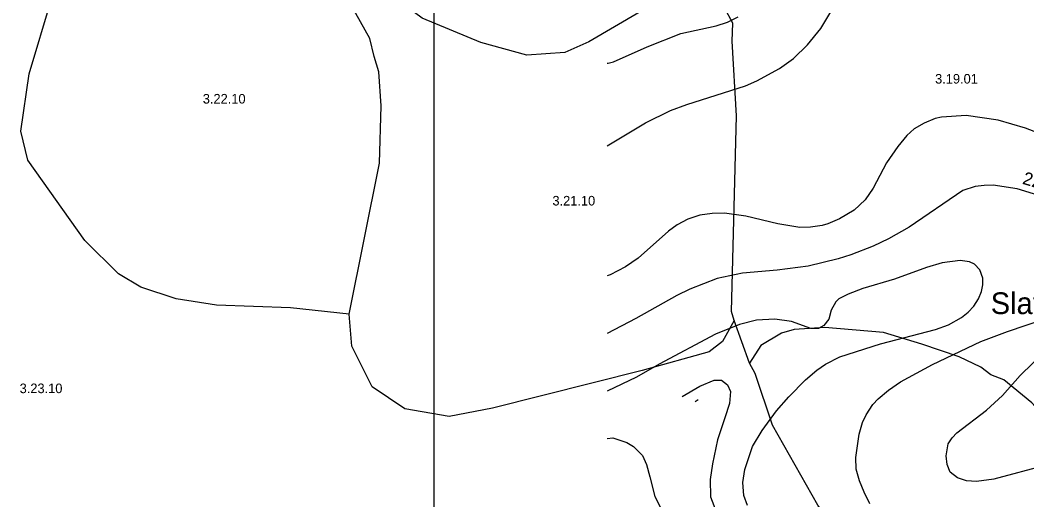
# Model space of a CAD drawing. Extents: x -662500 to -655523, y -1056000 to -1049993.
# Drawn here: x -662052 to -661264, y -1052458 to -1052083 of the extents above; entities that cross this region are included whole.
import ezdxf

# ---------------------------------------------------------------- set-up
doc = ezdxf.new("R2010")
doc.units = 0
for name, color, linetype in [('58', 7, 'Continuous'), ('Vrstva 24', 7, 'Continuous'), ('Vrstva 7', 7, 'Continuous'), ('Vrstva 9', 7, 'Continuous')]:
    doc.layers.add(name, color=color, linetype=linetype)

msp = doc.modelspace()

# ---------------------------------------------------------------- linework, layer by layer
at = {"layer": 'Vrstva 24'}
for points in [[(-661794, -1052312.5), (-661840, -1052307.5), (-661898, -1052305.5), (-661929.5, -1052300.5), (-661957, -1052291.5), (-661974.5, -1052281), (-662001, -1052255), (-662045.5, -1052192), (-662051, -1052169.5), (-662044.5, -1052124.5), (-662027, -1052066), (-662005.5, -1052025.5), (-661977.17, -1052000), (-661965.5, -1051989.5), (-661936, -1051957)], [(-661794, -1052312.5), (-661770.5, -1052194.5), (-661769, -1052149.5), (-661771, -1052123), (-661774.5, -1052111), (-661778, -1052097), (-661789, -1052077.5), (-661800, -1052057), (-661815.5, -1052036)], [(-661493, -1052317.5), (-661495, -1052310.5), (-661491, -1052157.5), (-661494.5, -1052099), (-661494, -1052085), (-661500.5, -1052073), (-661505, -1052066), (-661512.5, -1052062), (-661538.5, -1052064.5), (-661566.5, -1052076), (-661606.5, -1052099.5), (-661625.5, -1052108), (-661655, -1052110), (-661691, -1052100), (-661737, -1052081), (-661750, -1052071.5)], [(-661493, -1052317.5), (-661502, -1052334), (-661512.5, -1052342), (-661565, -1052356.5), (-661682, -1052386), (-661716, -1052392.5), (-661750.5, -1052386.5), (-661776, -1052369.5), (-661792, -1052337.5), (-661794, -1052312.5)], [(-661481, -1052351), (-661493, -1052317.5)], [(-661227, -1052423), (-661235.5, -1052409), (-661260, -1052382), (-661282, -1052364), (-661292, -1052360), (-661300, -1052354), (-661317, -1052346), (-661346, -1052336), (-661376, -1052327), (-661422, -1052323), (-661446, -1052324.5), (-661456, -1052327.5), (-661472, -1052337), (-661481, -1052351)], [(-661304, -1052572.5), (-661358, -1052540), (-661388.5, -1052512), (-661390.5, -1052507), (-661393, -1052508.5), (-661427.5, -1052462), (-661463, -1052399.5), (-661476.5, -1052359), (-661481, -1052351)]]:
    msp.add_lwpolyline(points, dxfattribs=at)
at = {"layer": 'Vrstva 7'}
for p, q in [((-661425.05, -1052089.09), (-661409.74, -1052063.58)), ((-661534.59, -1052093.06), (-661507.1, -1052087.11)), ((-661507.1, -1052087.11), (-661498.03, -1052084.13)), ((-661498.03, -1052084.13), (-661489.81, -1052079.88)), ((-661561.09, -1052103.41), (-661534.59, -1052093.06)), ((-661435.53, -1052101.85), (-661425.05, -1052089.09)), ((-661446.44, -1052112.48), (-661435.53, -1052101.85)), ((-661587.31, -1052115.17), (-661561.09, -1052103.41)), ((-661592.25, -1052116.21), (-661591.42, -1052116.16)), ((-661591.42, -1052116.16), (-661587.31, -1052115.17)), ((-661457.5, -1052120.41), (-661446.44, -1052112.48)), ((-661475.07, -1052130.05), (-661457.5, -1052120.41)), ((-661530.06, -1052148.47), (-661484.14, -1052134.02)), ((-661484.14, -1052134.02), (-661475.07, -1052130.05)), ((-661542.81, -1052153.29), (-661530.06, -1052148.47)), ((-661562.37, -1052162.93), (-661542.81, -1052153.29)), ((-661311.53, -1052157.26), (-661330.8, -1052158.53)), ((-661286.31, -1052160.94), (-661311.53, -1052157.26)), ((-661592.25, -1052180.9), (-661562.37, -1052162.93)), ((-661344.27, -1052163.21), (-661352.06, -1052167.6)), ((-661335.62, -1052159.53), (-661344.27, -1052163.21)), ((-661330.8, -1052158.53), (-661335.62, -1052159.53)), ((-661265.05, -1052167.18), (-661286.31, -1052160.94)), ((-661357.87, -1052172.71), (-661364.96, -1052181.35)), ((-661352.06, -1052167.6), (-661357.87, -1052172.71)), ((-661243.79, -1052175.26), (-661265.05, -1052167.18)), ((-661364.96, -1052181.35), (-661373.6, -1052194.25)), ((-661373.6, -1052194.25), (-661384.23, -1052214.09)), ((-661304.45, -1052212.81), (-661313.94, -1052215.79)), ((-661297.36, -1052211.82), (-661304.45, -1052212.81)), ((-661290.27, -1052211.68), (-661297.36, -1052211.82)), ((-661271.42, -1052214.65), (-661290.27, -1052211.68)), ((-661384.23, -1052214.09), (-661390.47, -1052223.16)), ((-661313.94, -1052215.79), (-661356.03, -1052244.55)), ((-661231.04, -1052226.7), (-661271.42, -1052214.65)), ((-661390.47, -1052223.16), (-661398.97, -1052231.23)), ((-661519.85, -1052235.06), (-661529.07, -1052238.18)), ((-661510.22, -1052233.78), (-661519.85, -1052235.06)), ((-661500.58, -1052233.5), (-661510.22, -1052233.78)), ((-661483.86, -1052235.77), (-661500.58, -1052233.5)), ((-661458.63, -1052242.01), (-661483.86, -1052235.77)), ((-661398.97, -1052231.23), (-661410.45, -1052238.04)), ((-661537.43, -1052242.71), (-661544.23, -1052247.67)), ((-661529.07, -1052238.18), (-661537.43, -1052242.71)), ((-661441.63, -1052244.7), (-661458.63, -1052242.01)), ((-661433.12, -1052244.55), (-661441.63, -1052244.7)), ((-661424.05, -1052243.28), (-661433.12, -1052244.55)), ((-661419.52, -1052242.01), (-661424.05, -1052243.28)), ((-661410.45, -1052238.04), (-661419.52, -1052242.01)), ((-661356.03, -1052244.55), (-661372.04, -1052253.62)), ((-661544.23, -1052247.67), (-661567.9, -1052268.65)), ((-661384.09, -1052259.29), (-661401.66, -1052266.24)), ((-661372.04, -1052253.62), (-661384.09, -1052259.29)), ((-661567.9, -1052268.65), (-661577.96, -1052275.59)), ((-661401.66, -1052266.24), (-661411.58, -1052269.36)), ((-661577.96, -1052275.59), (-661589.86, -1052281.69)), ((-661435.11, -1052275.02), (-661459.2, -1052278.14)), ((-661411.58, -1052269.36), (-661435.11, -1052275.02)), ((-661342.43, -1052276.16), (-661367.37, -1052285.23)), ((-661330.24, -1052272.47), (-661342.43, -1052276.16)), ((-661316.07, -1052270.49), (-661330.24, -1052272.47)), ((-661308.7, -1052271.62), (-661316.07, -1052270.49)), ((-661304.87, -1052273.32), (-661308.7, -1052271.62)), ((-661300.62, -1052277.86), (-661304.87, -1052273.32)), ((-661589.86, -1052281.69), (-661592.25, -1052282.54)), ((-661486.41, -1052280.41), (-661506.25, -1052284.66)), ((-661459.2, -1052278.14), (-661486.41, -1052280.41)), ((-661298.35, -1052284.38), (-661300.62, -1052277.86)), ((-661298.35, -1052289.48), (-661298.35, -1052284.38)), ((-661506.25, -1052284.66), (-661527.65, -1052292.88)), ((-661367.37, -1052285.23), (-661392.31, -1052292.6)), ((-661299.34, -1052294.86), (-661298.35, -1052289.48)), ((-661537.71, -1052297.84), (-661569.74, -1052315.98)), ((-661527.65, -1052292.88), (-661537.71, -1052297.84)), ((-661403.79, -1052296.85), (-661411.02, -1052300.68)), ((-661392.31, -1052292.6), (-661403.79, -1052296.85)), ((-661301.75, -1052300.53), (-661299.34, -1052294.86)), ((-661413.42, -1052302.94), (-661416.97, -1052309.32)), ((-661411.02, -1052300.68), (-661413.42, -1052302.94)), ((-661309.83, -1052311.02), (-661305.3, -1052306.2)), ((-661305.3, -1052306.2), (-661301.75, -1052300.53)), ((-661569.74, -1052315.98), (-661592.25, -1052327.67)), ((-661416.97, -1052309.32), (-661418.81, -1052316.55)), ((-661325.14, -1052320.8), (-661314.93, -1052315.13)), ((-661314.93, -1052315.13), (-661309.83, -1052311.02)), ((-661278.94, -1052326.04), (-661249.18, -1052315.98)), ((-661488.82, -1052320.66), (-661507.38, -1052328.17)), ((-661475.35, -1052317.26), (-661488.82, -1052320.66)), ((-661461.18, -1052316.41), (-661475.35, -1052317.26)), ((-661448.15, -1052318.39), (-661461.18, -1052316.41)), ((-661432.84, -1052323.77), (-661448.15, -1052318.39)), ((-661426.89, -1052323.77), (-661432.84, -1052323.77)), ((-661422.64, -1052321.37), (-661426.89, -1052323.77)), ((-661418.81, -1052316.55), (-661422.64, -1052321.37)), ((-661335.34, -1052324.62), (-661325.14, -1052320.8)), ((-661507.38, -1052328.17), (-661551.6, -1052351.55)), ((-661378.42, -1052335.68), (-661335.34, -1052324.62)), ((-661299.91, -1052333.98), (-661278.94, -1052326.04)), ((-661410.17, -1052345.88), (-661378.42, -1052335.68)), ((-661337.61, -1052351.98), (-661299.91, -1052333.98)), ((-661421.5, -1052351.69), (-661410.17, -1052345.88)), ((-661269.16, -1052360.62), (-661249.46, -1052341.21)), ((-661551.6, -1052351.55), (-661569.31, -1052361.9)), ((-661428.31, -1052356.37), (-661421.5, -1052351.69)), ((-661362.83, -1052365.44), (-661337.61, -1052351.98)), ((-661569.31, -1052361.9), (-661592.25, -1052372.88)), ((-661437.09, -1052364.02), (-661428.31, -1052356.37)), ((-661283.05, -1052376.07), (-661269.16, -1052360.62)), ((-661533.51, -1052376.96), (-661519.74, -1052368.98)), ((-661519.74, -1052368.98), (-661508.51, -1052364.27)), ((-661508.51, -1052364.27), (-661502.71, -1052364.27)), ((-661502.71, -1052364.27), (-661498, -1052367.9)), ((-661498, -1052367.9), (-661495.83, -1052372.97)), ((-661450.13, -1052377.2), (-661437.09, -1052364.02)), ((-661372.04, -1052371.96), (-661362.83, -1052365.44)), ((-661495.83, -1052372.97), (-661496.55, -1052382.39)), ((-661459.77, -1052388.26), (-661450.13, -1052377.2)), ((-661384.37, -1052383.3), (-661380.26, -1052378.76)), ((-661380.26, -1052378.76), (-661372.04, -1052371.96)), ((-661295.52, -1052387.69), (-661283.05, -1052376.07)), ((-661523.4, -1052380.75), (-661520.95, -1052379.4)), ((-661496.55, -1052382.39), (-661500.31, -1052393.69)), ((-661389.76, -1052391.37), (-661384.37, -1052383.3)), ((-661500.31, -1052393.69), (-661505.82, -1052410.93)), ((-661470.96, -1052403.42), (-661459.77, -1052388.26)), ((-661392.45, -1052397.18), (-661389.76, -1052391.37)), ((-661318.62, -1052405.4), (-661295.52, -1052387.69)), ((-661395, -1052406.4), (-661392.45, -1052397.18)), ((-661592.25, -1052409.83), (-661587.94, -1052409.26)), ((-661587.94, -1052409.26), (-661576.98, -1052412.84)), ((-661478.47, -1052416.17), (-661470.96, -1052403.42)), ((-661397.69, -1052424.68), (-661395, -1052406.4)), ((-661325.42, -1052414.05), (-661322.44, -1052409.37)), ((-661322.44, -1052409.37), (-661318.62, -1052405.4)), ((-661576.98, -1052412.84), (-661571.55, -1052416.1)), ((-661571.55, -1052416.1), (-661564.66, -1052422.99)), ((-661505.82, -1052410.93), (-661509.93, -1052429.5)), ((-661484.57, -1052434.03), (-661478.47, -1052416.17)), ((-661326.98, -1052423.26), (-661325.42, -1052414.05)), ((-661564.66, -1052422.99), (-661561.4, -1052430.24)), ((-661397.41, -1052433.75), (-661397.69, -1052424.68)), ((-661326.27, -1052430.06), (-661326.98, -1052423.26)), ((-661561.4, -1052430.24), (-661558.87, -1052439.66)), ((-661509.93, -1052429.5), (-661511.64, -1052441.91)), ((-661486.12, -1052444.23), (-661484.57, -1052434.03)), ((-661394.86, -1052442.82), (-661397.41, -1052433.75)), ((-661324, -1052436.16), (-661326.27, -1052430.06)), ((-661248.89, -1052430.77), (-661289.71, -1052441.54)), ((-661558.87, -1052439.66), (-661554.88, -1052455.25)), ((-661511.64, -1052441.91), (-661511.35, -1052455.43)), ((-661318.2, -1052440.49), (-661324, -1052436.16)), ((-661311.1, -1052442.82), (-661318.2, -1052440.49)), ((-661289.71, -1052441.54), (-661303.31, -1052443.38)), ((-661485.28, -1052454.44), (-661486.12, -1052444.23)), ((-661391.32, -1052451.89), (-661394.86, -1052442.82)), ((-661303.31, -1052443.38), (-661311.1, -1052442.82)), ((-661554.88, -1052455.25), (-661549.45, -1052465.76)), ((-661511.35, -1052455.43), (-661506.82, -1052467.76)), ((-661482.58, -1052462.09), (-661485.28, -1052454.44)), ((-661386.64, -1052460.81), (-661391.32, -1052451.89))]:
    msp.add_line(p, q, dxfattribs=at)
at = {"layer": 'Vrstva 9'}
msp.add_line((-661727.53, -1054263.7), (-661727.53, -1050947.21), dxfattribs=at)

# ---------------------------------------------------------------- texts
at = {"layer": '58'}
msp.add_text('Slatinek', height=17, dxfattribs=at).set_placement((-661292.18, -1052312.5))
at = {"layer": 'Vrstva 24'}
for s, p in [('3.19.01', (-661335.71, -1052132.19)), ('3.22.10', (-661908.63, -1052147.81)), ('3.21.10', (-661635.09, -1052227.56)), ('3.23.10', (-662051.91, -1052374.33))]:
    msp.add_text(s, height=7.5, dxfattribs=at).set_placement(p)
at = {"layer": 'Vrstva 7'}
msp.add_text('229', height=10, rotation=343.39281, dxfattribs=at).set_placement((-661267.95, -1052210.47))

doc.saveas('drawing.dxf')
